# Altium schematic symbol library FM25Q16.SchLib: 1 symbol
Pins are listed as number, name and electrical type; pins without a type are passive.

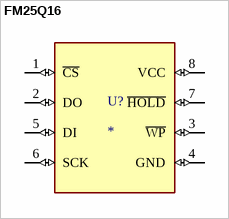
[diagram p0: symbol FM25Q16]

## FM25Q16
designator U?
Serial Flash Memory with 4KB Sectors SPI SOIC-8; MP: FM25W256-G; MF: Cypress Semiconductor
footprint FM25Q16
pins: 1 ~{CS} (io), 2 DO (io), 3 ~{WP} (io), 4 GND (io), 5 DI (io), 6 SCK (io), 7 ~{HOLD} (io), 8 VCC (io)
